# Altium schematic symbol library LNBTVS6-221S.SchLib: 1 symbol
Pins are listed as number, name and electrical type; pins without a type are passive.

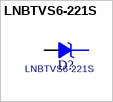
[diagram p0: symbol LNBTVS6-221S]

## LNBTVS6-221S
designator D?
footprint ST_SMC
pins: 1 K, 2 A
